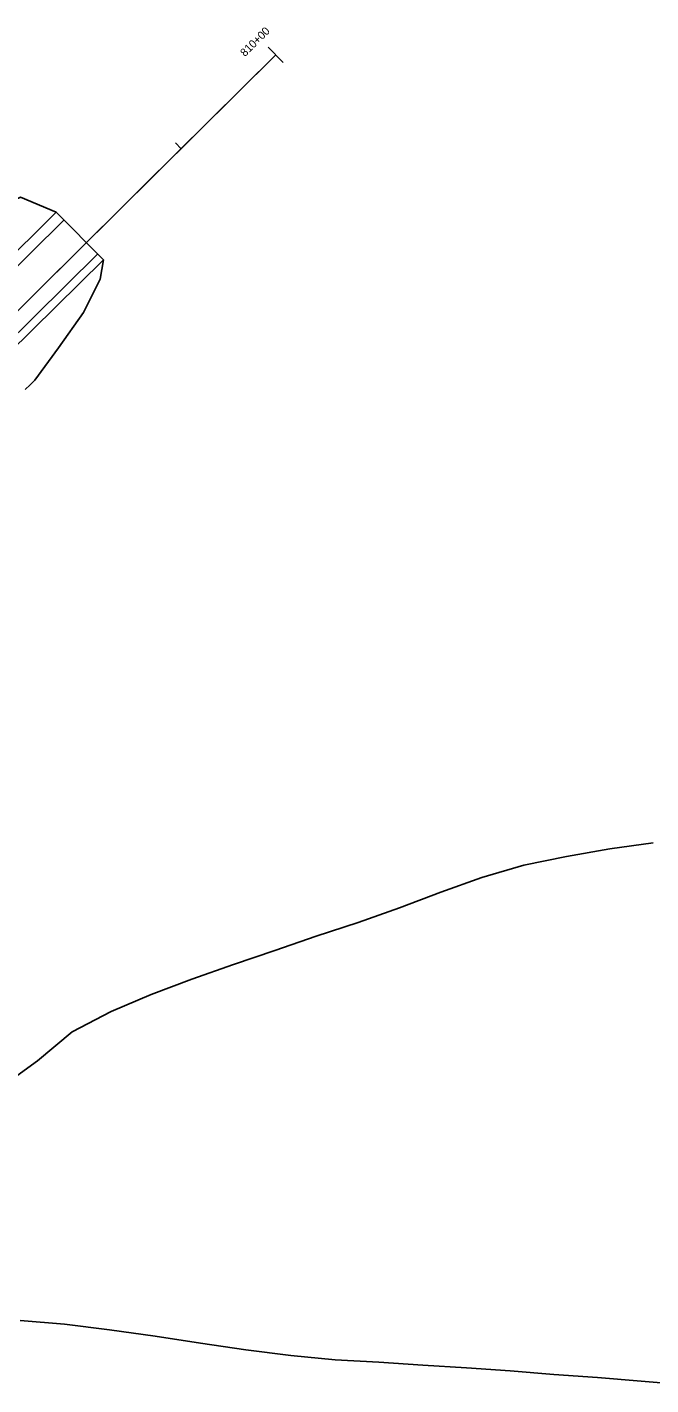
# Model space of a CAD drawing. Extents: x 1237212 to 1293764, y 379349 to 410301.
# Drawn here: x 1283981 to 1284449, y 403954 to 404971 of the extents above; entities that cross this region are included whole.
import ezdxf

# ---------------------------------------------------------------- set-up
doc = ezdxf.new("R2010")
doc.units = 0
for name, color, linetype in [('B-Tbl-Title Block', 7, 'Continuous'), ('B-Title Block (No Plot)', 7, 'Continuous'), ('R_Axis_Annotation', 7, 'Continuous'), ('R_Exist Surface', 7, 'Continuous'), ('R_Grid Annot', 7, 'Continuous'), ('R_Shld', 7, 'Continuous')]:
    doc.layers.add(name, color=color, linetype=linetype)

msp = doc.modelspace()

# ---------------------------------------------------------------- linework, layer by layer
at = {"layer": 'B-Tbl-Title Block'}
for p, q in [((1284003, 404832.6), (1284038.6, 404796.7)), ((1283937.8, 404756.4), (1284008.9, 404826.6)), ((1283963.1, 404730.8), (1284034.2, 404801.1))]:
    msp.add_line(p, q, dxfattribs=at)
at = {"layer": 'B-Title Block (No Plot)'}
for p, q in [((1283723.7, 404510.3), (1284167.7, 404950.5)), ((1283723.7, 404510.3), (1284167.7, 404950.5)), ((1283725.5, 404512.2), (1284086.2, 404869.7))]:
    msp.add_line(p, q, dxfattribs=at)
at = {"layer": 'R_Axis_Annotation'}
for points in [[(1283962.6, 404177.2), (1283989.1, 404196.5), (1284015, 404218.2), (1284044.3, 404233.5), (1284074.2, 404246.2), (1284104.7, 404257.6), (1284135.9, 404268.5), (1284167, 404279.2), (1284198, 404289.8), (1284229.4, 404300.2), (1284260.4, 404311.2), (1284291.3, 404322.8), (1284322.1, 404333.9), (1284353.5, 404343.1), (1284385.7, 404349.6), (1284418, 404355.2), (1284450.5, 404359.9)], [(1284474.2, 403953.5), (1284441.5, 403956.3), (1284408.9, 403959), (1284376.1, 403961.4), (1284343.3, 403964), (1284310.7, 403966.2), (1284277.8, 403968.4), (1284245, 403970.5), (1284212.3, 403972.3), (1284179.1, 403975.5), (1284145.3, 403979.7), (1284111.3, 403984.8), (1284077.2, 403989.9), (1284043.1, 403994.7), (1284009.3, 403998.9), (1283976, 404001.7)]]:
    msp.add_lwpolyline(points, dxfattribs=at)
at = {"layer": 'R_Exist Surface'}
for points in [[(1283899.6, 404794.9), (1283921.4, 404811.9), (1283946.6, 404830.1), (1283976.4, 404843.7), (1284003, 404832.6)], [(1283987.2, 404706.5), (1284004.8, 404730.9), (1284023.5, 404757.2), (1284036.2, 404782.2), (1284038.6, 404796.7)], [(1283979.9, 404699.6), (1283983.6, 404703), (1283987.2, 404706.5)]]:
    msp.add_lwpolyline(points, dxfattribs=at)
at = {"layer": 'R_Grid Annot'}
for points in [[(1284162.1, 404956.2), (1284173.3, 404944.8)], [(1284162.1, 404956.2), (1284173.3, 404944.8)], [(1284092.5, 404884.4), (1284096.7, 404880.1)], [(1284092.5, 404884.4), (1284096.7, 404880.1)], [(1284021.4, 404814), (1284025.7, 404809.7)], [(1284021.4, 404814), (1284025.7, 404809.7)]]:
    msp.add_lwpolyline(points, dxfattribs=at)
at = {"layer": 'R_Shld'}
for p, q in [((1284068, 404851.7), (1284167.7, 404950.5)), ((1283932.1, 404762), (1284003, 404832.6)), ((1283967.3, 404726.5), (1284038.6, 404796.7))]:
    msp.add_line(p, q, dxfattribs=at)

# ---------------------------------------------------------------- texts
at = {"layer": 'R_Grid Annot'}
msp.add_text('810+00', height=6, rotation=44.75, dxfattribs=at).set_placement((1284144.6, 404948.7))

doc.saveas('drawing.dxf')
